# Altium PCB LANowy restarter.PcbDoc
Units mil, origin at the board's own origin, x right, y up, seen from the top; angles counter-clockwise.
Board outline 6000 x 4000 mil, 2 copper layers (Top Layer, Bottom Layer); 23 components, 17 nets, 67 pads, 20 vias.
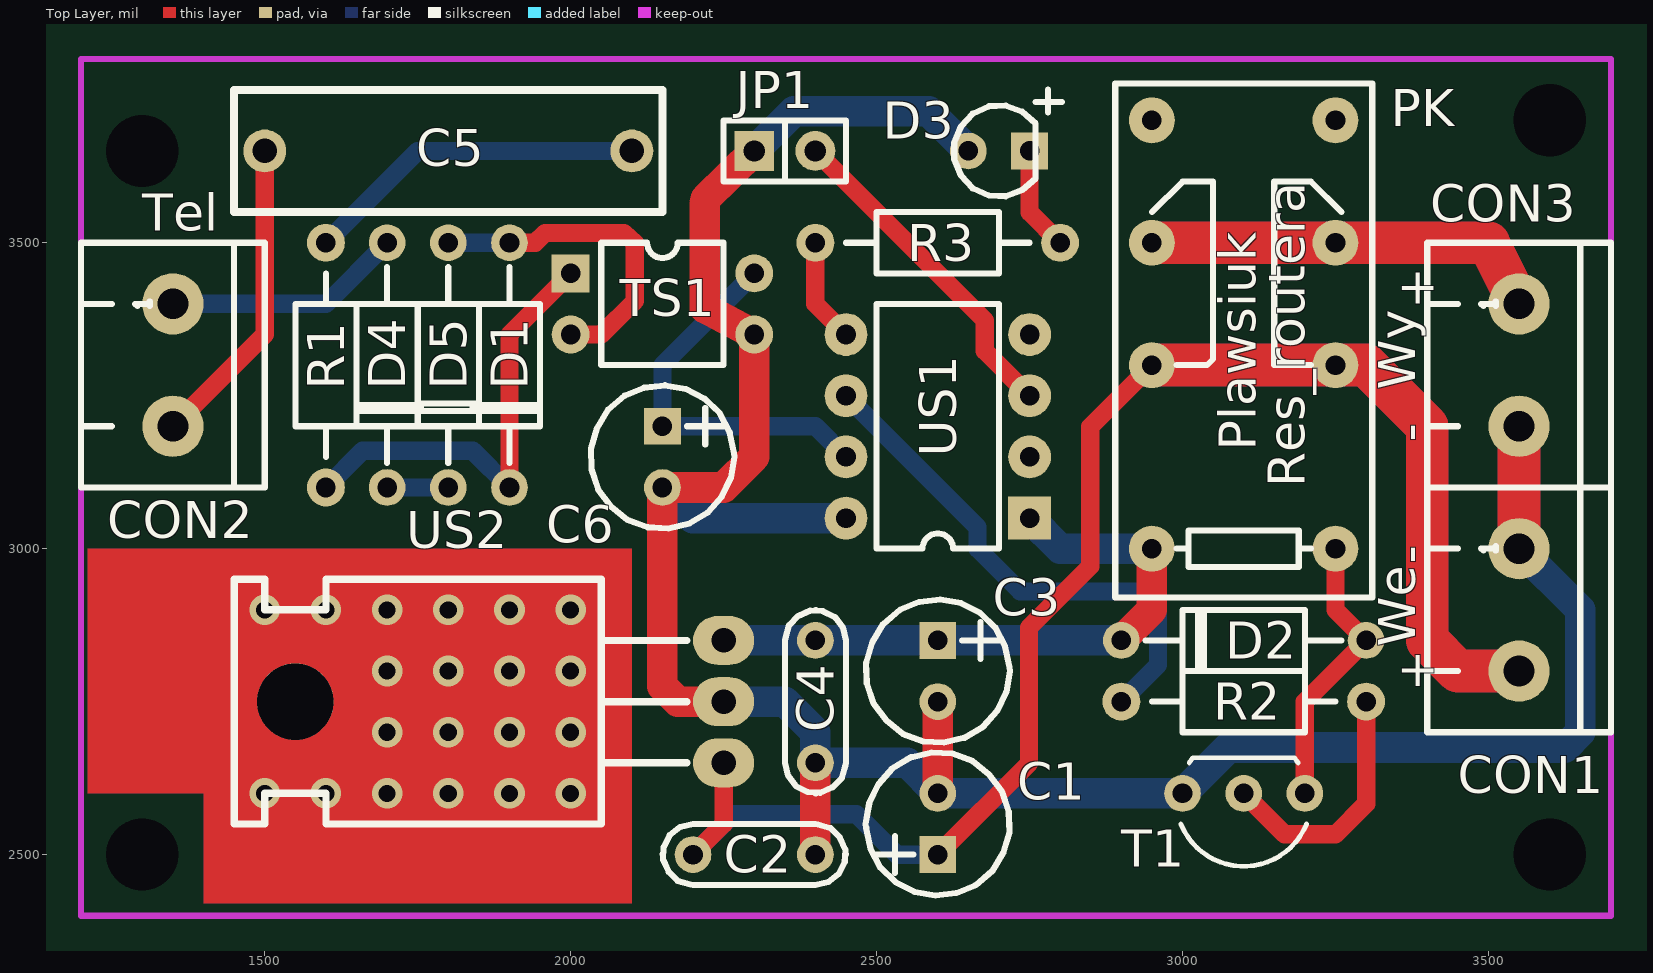
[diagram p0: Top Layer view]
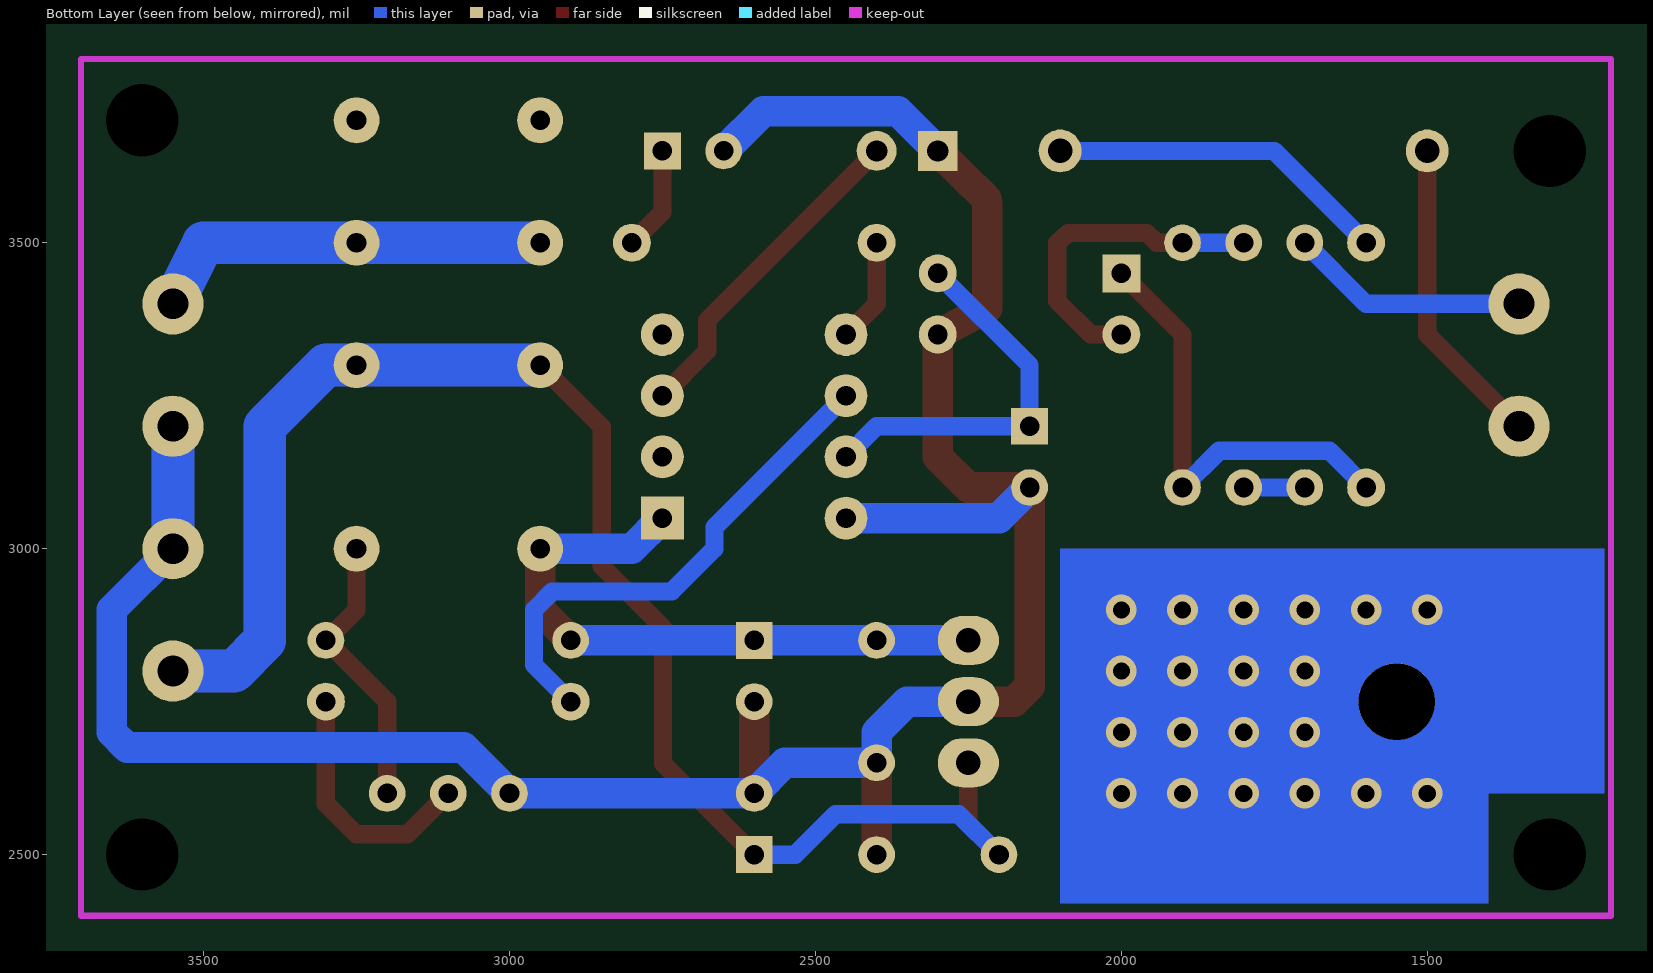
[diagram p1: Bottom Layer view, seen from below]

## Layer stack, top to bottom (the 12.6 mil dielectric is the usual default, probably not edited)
Top Layer: signal copper 1.4
Dielectric: dielectric 12.6, FR-4, Dk 4.8
Bottom Layer: signal copper 1.4

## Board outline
1000,1000 7000,1000 7000,5000 1000,5000

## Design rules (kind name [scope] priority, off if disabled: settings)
Clearance [All] p1: gap=15
ComponentClearance [All] p1: gap=10 collisioncheckmode=0 verticalgap=10
PolygonConnect [All] p1: connectstyle=Relief reliefconductorwidth=10 reliefentries=4 polygonreliefangle="90 Angle"
RoutingVias [All] p1: holewidth=28 width=50 viastyle="Through Hole" minholewidth=28 minwidth=50 maxholewidth=28 maxwidth=50
SolderMaskExpansion [All] p1: expansion=4
TestPointUsage [All] p1: valid=0 allowmultiple=FALSE
Testpoint [All] p1: side=15 testpointundercomponent=TRUE minsize=40 maxsize=100 preferedsize=60 minholesize=0 maxholesize=40 preferedholesize=32 testpointgrid=1 style=1023 order=0-112345678
Width Width_1 [InNet('GND')  or  InNet('vcc')] p1: maxlimit=50 minlimit=10 preferedwidth=50
Width [All] p2: maxlimit=40 minlimit=10 preferedwidth=30
17 further rules are at their usual default settings.

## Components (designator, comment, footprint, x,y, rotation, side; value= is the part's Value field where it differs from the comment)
C1 "47u" elektr1 2600,2500 r180 top
C2 "100n" cap1 2300,2500 r0 top
C3 "47u" elektr1 2600,2850 r0 top
C4 "100n" cap1 2400,2750 r270 top
C5 "220n/250V" RAD-05 1800,3650 r90 top
C6 "4,7u" elektr1 2150,3200 r0 top
CON1 "ARK2-5mm" con2-5 3550,2900 r90 top
CON2 "ARK2-5mm" con2-5 1350,3300 r90 top
CON3 "ARK2-5mm" con2-5 3550,3300 r90 top
D1 "1N4148" dioda 1900,3300 r270 top (schematic designator D6)
D2 "1N4007" dioda 3100,2850 r180 top
D3 "LED3" led3 2750,3650 r90 top
D4 "DZ15V" DIODa 1700,3300 r270 top
D5 "DZ15V" dioda 1800,3300 r90 top
JP1 "" SIP2 2300,3650 r0 top
PK "przek_3A" przek_3A 3250,3000 r90 top
R1 "10k" r 1600,3300 r270 top
R2 "4,7k" r 3100,2750 r0 top
R3 "330R" r 2600,3500 r180 top
T1 "BC547" to-92c 3200,2600 r270 top
TS1 "PC817" dip4 2000,3450 r0 top
US1 "PIC12F629" dip8 2750,3050 r180 top
US2 "LM2940" TO-220 2250,2650 r90 top

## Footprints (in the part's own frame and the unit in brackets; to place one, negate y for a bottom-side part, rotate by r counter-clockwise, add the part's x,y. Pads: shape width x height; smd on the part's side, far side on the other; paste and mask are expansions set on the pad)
cap1 [mil]
  round 60 hole 32: 1(-100,0) 2(100,0)
  silkscreen extent -150,-50 150,50
con2-5 [mil]
  round 100 hole 50: 1(100,0) 2(-100,0)
  silkscreen extent -200,-150 200,150
dioda [mil]
  round 60 hole 32: 1(-200,0) 2(200,0)
  silkscreen extent -160,-50 160,50
DIODa [mil]
  round 60 hole 32: 1(-200,0) 2(200,0)
  silkscreen extent -160,-50 160,50
dip4 [mil]
  rect 62x62 hole 32: 1(0,0)
  round 62 hole 32: 2(0,-100) 3(300,-100) 4(300,0)
  silkscreen extent 50,-150 250,50
dip8 [mil]
  rect 70x70 hole 32: 1(0,0)
  round 70 hole 32: 2(0,-100) 3(0,-200) 4(0,-300) 5(300,-300) 6(300,-200) 7(300,-100) 8(300,0)
  silkscreen extent 50,-350 250,50
elektr1 [mil]
  rect 60x60 hole 32: 1(0,0)
  round 60 hole 32: 2(0,-100)
  silkscreen extent -117,-167 118,67
led3 [mil]
  rect 60x60 hole 32: 1(0,0)
  round 60 hole 32: 2(0,100)
  silkscreen extent -74,-53 100,123
przek_3A [mil]
  round 75 hole 32: 1(0,0) 4(300,0) 6(500,0) 8(700,0) 9(700,300) 11(500,300) 13(300,300) 16(0,300)
  silkscreen extent -80,-60 760,360
r [mil]
  round 62 hole 32: 1(-200,0) 2(200,0)
  silkscreen extent -150,-50 150,50
RAD-05 [mil]
  round 70 hole 40: 1(0,300) 2(0,-300)
  silkscreen extent -100,-350 100,350
SIP2 [mil]
  rect 65x65 hole 35: 1(0,0)
  round 65 hole 35: 2(100,0)
  silkscreen extent -50,-50 150,50
to-92c [mil]
  round 60 hole 32: 1(0,0) 2(0,-100) 3(0,-200)
  silkscreen extent -58,-203 119,3
TO-220 [mil]
  oval 80x100 hole 40: 1(0,0) 2(100,0) 3(200,0)
  round 125 hole 125: ""(100,700)
  silkscreen extent -100,60 300,800

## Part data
C1 C3 C6: library part ELECTRO2, "Electrolytic Capacitor"
C2 C4 C5: library part CAP, "Capacitor"
CON1 CON3: library part CON2, "Connector"
CON2: library part RJ11
D1 D2: library part DIODE, "Diode"
D3: library part LED
D4 D5: library part ZENER1, "Zener Diode"
JP1: library part JUMPER
R1 R2 R3: library part RES2
T1: library part NPN1, "NPN Transistor"
US2: library part VOLTREG

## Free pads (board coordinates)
  round 60 hole 118.11: 0(1300,3650) 1(1300,2500) 2(3600,2500) 3(3600,3700)

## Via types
v1: diameter 50, hole 28, Top Layer to Bottom Layer, 20 vias

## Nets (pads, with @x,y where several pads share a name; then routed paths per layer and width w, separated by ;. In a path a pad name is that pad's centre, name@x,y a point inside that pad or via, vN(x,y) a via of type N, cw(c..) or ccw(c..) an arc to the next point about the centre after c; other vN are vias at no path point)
GND: C1.2 C2.2 C3.2 C4.2 C6.2 CON1.1 CON3.2 D3.2 JP1.1 T1.3 TS1.3 US1.8 US2.2 | length 4486.8
  Top Layer w50: US2.2 2175,2750 2150,2775 C6.2 2250,3100 2300,3150 TS1.3 2219,3393 2219,3563 2221,3572 JP1.1 ; C2.2 C4.2 ; C1.2 C3.2
  Top Layer w70: CON1.1 CON3.2
  Bottom Layer w50: C6.2 2200,3050 US1.8 ; US2.2 2350,2750 2400,2700 C4.2 2550,2650 C1.2 T1.3 3075,2675 3625,2675 3650,2700 3650,2900 CON1.1 ; JP1.1 2365,3715 2585,3715 D3.2
  Bottom Layer w70: CON1.1 CON3.2
NetC1_1: C1.1 C2.1 CON1.2 PK.4 PK.13 US2.1 | length 3594.6
  Top Layer w30: C2.1 2250,2550 US2.1 ; C1.1 2749,2649 2749,2871 2849,2971 2849,3199 PK.13
  Top Layer w70: PK.13 PK.4 3300,3300 3400,3200 3400,2850 3450,2800 CON1.2
  Bottom Layer w30: C2.1 2266,2566 2467,2566 2533,2500 C1.1
  Bottom Layer w70: PK.13 PK.4 3300,3300 3400,3200 3400,2850 3450,2800 CON1.2
NetC5_1: C5.1 CON2.2 | length 512.1
  Top Layer w30: CON2.2 1500,3350 C5.1
NetC5_2: C5.2 R1.1 | length 562.1
  Bottom Layer w30: R1.1 1750,3650 C5.2
NetC6_1: C6.1 TS1.4 US1.7 | length 632.8
  Bottom Layer w30: TS1.4 2150,3300 C6.1 2400,3200 US1.7
NetCON2_1: CON2.1 D4.1 | length 391.4
  Bottom Layer w30: CON2.1 1600,3400 D4.1
NetCON3_1: CON3.1 PK.6 PK.11 | length 1323.6
  Top Layer w70: PK.11 PK.6 3500,3500 CON3.1
  Bottom Layer w70: PK.11 PK.6 3500,3500 CON3.1
NetD2_1: D2.1 PK.1 T1.1 | length 462.1
  Top Layer w30: T1.1 3200,2750 D2.1 3250,2900 PK.1
NetD3_1: D3.1 R3.1 | length 170.7
  Top Layer w30: D3.1 2750,3550 R3.1
NetD4_2: D4.2 D5.1 | length 100
  Bottom Layer w30: D4.2 D5.1
NetD5_2: D1.1 D5.2 TS1.2 | length 540.5
  Top Layer w30: D1.1 1942,3500 1958,3516 2087,3516 2105,3500 2105,3405 2050,3350 TS1.2
  Bottom Layer w30: D5.2 D1.1
NetD6_2: D1.2 R1.2 TS1.1 | length 741.1
  Top Layer w30: D1.2 1900,3350 TS1.1
  Bottom Layer w30: R1.2 1660,3160 1840,3160 D1.2
NetJP1_2: JP1.2 US1.3 | length 545
  Top Layer w30: JP1.2 2677,3373 2677,3323 US1.3
NetR2_1: R2.1 US1.6 | length 850.3
  Bottom Layer w30: US1.6 2665,3035 2665,3000 2735,2930 2930,2930 2960,2900 2960,2810 R2.1
NetR2_2: R2.2 T1.2 | length 415.5
  Top Layer w30: T1.2 3167,2533 3250,2533 3300,2583 R2.2
NetR3_2: R3.2 US1.5 | length 170.7
  Top Layer w30: R3.2 2400,3400 US1.5
VCC: C3.1 C4.1 D2.2 PK.16 US1.1 US2.3 | length 1041.4
  Top Layer w50: D2.2 2950,2900 PK.16
  Bottom Layer w50: US2.3 C4.1 C3.1 D2.2 ; US1.1 2800,3000 PK.16
pads on no net: PK.8 PK.9 US1.2 US1.4 US2.
copper on no net:
  other v1: 1500,2600 1600,2600 1700,2600 1800,2600 1900,2600 2000,2600 1700,2700 1800,2700 1900,2700 2000,2700 1700,2800 1800,2800 1900,2800 2000,2800 1500,2900 1600,2900 1700,2900 1800,2900 1900,2900 2000,2900

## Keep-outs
Keep-Out Layer:
  lines w10: 1200,2400 3700,2400 3700,3800 1200,3800 1200,2400

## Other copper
Multi-Layer:
  rectangle: 1400,2420 2100,3000
  rectangle: 1210,2600 1400,3000

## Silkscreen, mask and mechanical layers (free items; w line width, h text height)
Top Overlay:
  text "Tel" at 1300,3520 h60
  text "+" at 3350,3400 h60
  text "Wy" at 3380,3260 h60 r90
  text "-" at 3400,3175 h60 r90
  text "Plawsiuk" at 3120,3160 h60 r90
  text "Res_routera" at 3200,3100 h60 r90
  text "-" at 3400,2975 h60 r90
  text "We" at 3380,2840 h60 r90
  text "+" at 3350,2775 h60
